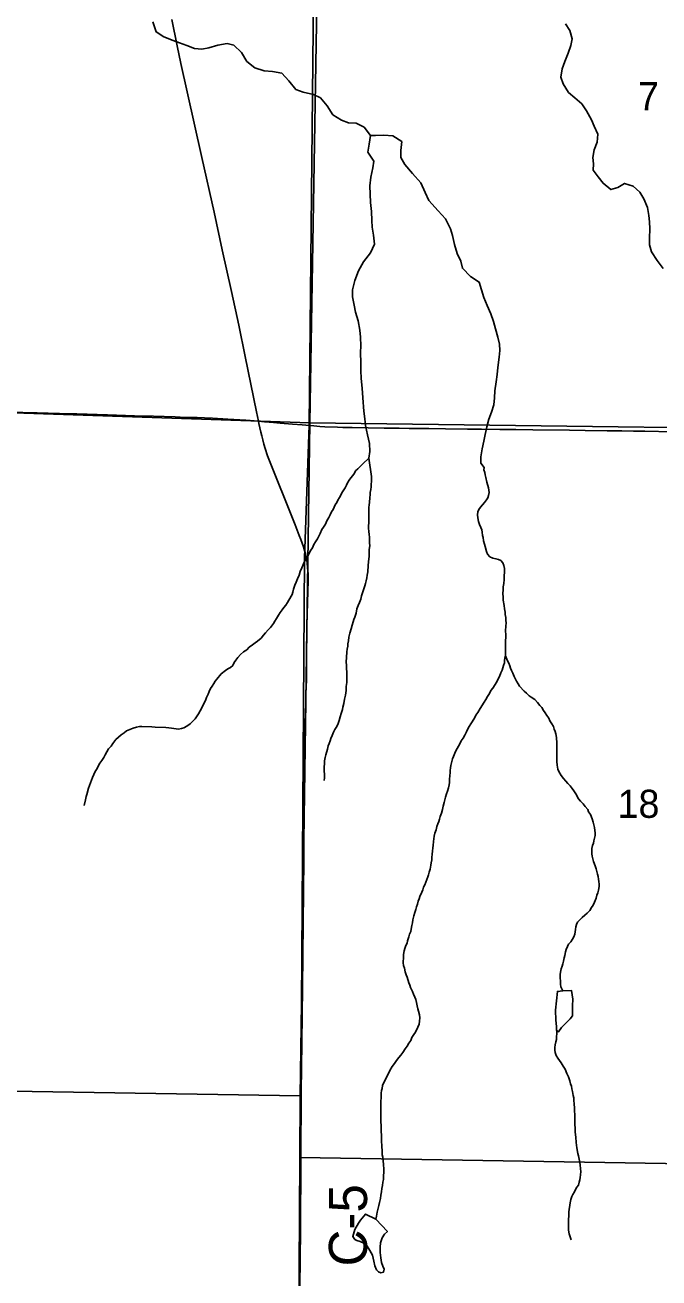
# Model space of a CAD drawing. Extents: x 0 to 34, y 0 to 22.
# Drawn here: x 3.044 to 3.988, y 15.009 to 16.874 of the extents above; entities that cross this region are included whole.
import ezdxf

# ---------------------------------------------------------------- set-up
doc = ezdxf.new("R2010")
doc.units = 0
for name, color, linetype in [('GM_X_Corporation', 7, 'Continuous'), ('GM_X_County_Road', 7, 'Continuous'), ('GM_X_County_Road_Text', 7, 'Continuous'), ('GM_X_Minor_River', 7, 'Continuous'), ('GM_X_Section_Text', 7, 'Continuous')]:
    doc.layers.add(name, color=color, linetype=linetype)

msp = doc.modelspace()

# ---------------------------------------------------------------- linework, layer by layer
at = {"layer": 'GM_X_Corporation'}
for points in [[(2.1, 18.3932), (2.1, 14.1), (3.4463, 14.1), (3.448, 14.3179), (3.4516, 14.7743), (3.4533, 15.0461), (3.4601, 16.0804), (3.4672, 16.2781), (3.4754, 17.1134)], [(3.4754, 17.1134), (3.4672, 16.2781), (3.4601, 16.0804), (3.4533, 15.0461), (3.4516, 14.7743), (3.448, 14.3179), (3.4463, 14.1), (8.9, 14.1)]]:
    msp.add_lwpolyline(points, dxfattribs=at)
for points in [[(3.4847, 17.2912), (3.4681, 16.2816), (2.4544, 16.3158), (2.4791, 17.2994)], [(4.475, 17.2762), (4.463, 16.2688), (3.4681, 16.2816), (3.4847, 17.2912)], [(2.4544, 16.3158), (3.4681, 16.2816), (3.4534, 15.28), (2.4405, 15.2964)], [(3.4681, 16.2816), (4.463, 16.2688), (4.4514, 15.172), (3.4532, 15.1884), (3.4534, 15.28)], [(2.4405, 15.2964), (3.4534, 15.28), (3.4532, 15.1884), (3.4477, 14.2699), (2.4377, 14.2835)], [(3.4532, 15.1884), (4.4514, 15.172), (4.4501, 14.1693), (3.4483, 14.1786), (3.4477, 14.2699)]]:
    msp.add_lwpolyline(points, close=True, dxfattribs=at)
at = {"layer": 'GM_X_County_Road'}
for points in [[(3.4613, 16.087), (3.4601, 16.0918), (3.4584, 16.0969), (3.4564, 16.1027), (3.4546, 16.1079), (3.4522, 16.1142), (3.446, 16.1298), (3.4052, 16.2326), (3.4015, 16.2433), (3.3996, 16.2499), (3.3979, 16.2564), (3.3965, 16.2623), (3.3952, 16.2677), (3.3935, 16.2744), (3.392, 16.2808), (3.3914, 16.2841), (3.3886, 16.2981), (3.3718, 16.3806), (3.3623, 16.427), (3.3513, 16.4769), (3.3376, 16.5393), (3.3254, 16.5952), (3.307, 16.6764), (3.2853, 16.7744), (3.2761, 16.8163), (3.2703, 16.8429), (3.2623, 16.8819)], [(3.0196, 16.2974), (3.0619, 16.2965), (3.0954, 16.2956), (3.1209, 16.2949), (3.1668, 16.2935), (3.2072, 16.2922), (3.2351, 16.2914), (3.2674, 16.2904), (3.2824, 16.2898), (3.3003, 16.2895), (3.3113, 16.2892), (3.3233, 16.2887), (3.3461, 16.2871), (3.3726, 16.2855), (3.3914, 16.2841), (3.4007, 16.2834), (3.4137, 16.2824), (3.4236, 16.2814), (3.4421, 16.2798), (3.4564, 16.2785), (3.4674, 16.2775)], [(3.4674, 16.2775), (3.4738, 16.277), (3.4831, 16.2763), (3.4905, 16.2759), (3.5091, 16.2751), (3.5172, 16.2748), (3.5308, 16.2746), (3.5787, 16.2739), (3.601, 16.2736), (3.6159, 16.2734), (3.6451, 16.2731), (3.67, 16.2728), (3.7029, 16.2724), (3.7234, 16.2721), (3.7507, 16.2719), (3.7749, 16.2718), (3.7998, 16.2715), (3.8544, 16.2707), (3.878, 16.2704), (3.9109, 16.2697), (3.9327, 16.2696), (3.9501, 16.2693), (3.9668, 16.2691), (4.0078, 16.2685)], [(3.4531, 14.9957), (3.4539, 15.0799), (3.4548, 15.1862), (3.4552, 15.2854), (3.4563, 15.3594), (3.4571, 15.4414), (3.4592, 15.6323), (3.4597, 15.7352), (3.4601, 15.8048), (3.4618, 15.8641), (3.4622, 15.8783), (3.4629, 15.899), (3.4629, 15.9319), (3.4636, 15.981), (3.4654, 16.0471), (3.4654, 16.0576), (3.4647, 16.0652), (3.4638, 16.0737), (3.4627, 16.0805), (3.4613, 16.087)]]:
    msp.add_lwpolyline(points, dxfattribs=at)
at = {"layer": 'GM_X_Minor_River'}
for points in [[(3.2344, 16.8784), (3.2394, 16.8635), (3.2505, 16.856), (3.2644, 16.8508), (3.2742, 16.8471), (3.2851, 16.8434), (3.2964, 16.839), (3.3074, 16.838), (3.3176, 16.8396), (3.331, 16.8438), (3.3451, 16.8461), (3.3549, 16.8436), (3.3664, 16.8327), (3.3744, 16.8196), (3.3863, 16.8102), (3.4002, 16.8053), (3.4124, 16.8047), (3.4263, 16.8021), (3.4367, 16.7908), (3.4474, 16.778), (3.4579, 16.774), (3.4737, 16.7702), (3.4838, 16.7654), (3.4938, 16.7534), (3.5022, 16.7403), (3.5152, 16.732), (3.5254, 16.7283), (3.5371, 16.7277), (3.5491, 16.7217), (3.5583, 16.7093), (3.5561, 16.6965), (3.5543, 16.6844), (3.5634, 16.6713), (3.562, 16.6614), (3.559, 16.6475), (3.5572, 16.6346), (3.5576, 16.6221), (3.5585, 16.6096), (3.5597, 16.5963), (3.5601, 16.583), (3.5606, 16.5727), (3.5629, 16.5609), (3.5645, 16.5476), (3.5581, 16.5345), (3.5479, 16.5215), (3.5404, 16.508), (3.5351, 16.4937), (3.5313, 16.4798), (3.5314, 16.4691), (3.5342, 16.4566), (3.5362, 16.4463), (3.54, 16.4337), (3.5424, 16.4196), (3.5436, 16.4093), (3.5437, 16.3964), (3.5434, 16.3865), (3.5438, 16.371), (3.5439, 16.3596), (3.5444, 16.3478), (3.5459, 16.3334), (3.5467, 16.319), (3.5485, 16.2992), (3.5497, 16.2874), (3.551, 16.2775), (3.554, 16.2638), (3.5567, 16.2508), (3.5572, 16.2391), (3.5558, 16.2292)], [(3.8488, 16.8755), (3.855, 16.8655), (3.8586, 16.8533), (3.8565, 16.8431), (3.8525, 16.8318), (3.8477, 16.8194), (3.8437, 16.8085), (3.8416, 16.796), (3.8452, 16.7864), (3.8529, 16.7734), (3.8627, 16.7653), (3.8727, 16.7564), (3.8798, 16.746), (3.8871, 16.7326), (3.8915, 16.723), (3.8966, 16.7115), (3.896, 16.6994), (3.8912, 16.6878), (3.8895, 16.6768), (3.8901, 16.6673), (3.8899, 16.6575), (3.8973, 16.6478), (3.9047, 16.6382), (3.9163, 16.6289), (3.9266, 16.6318), (3.9366, 16.638), (3.9494, 16.634), (3.9591, 16.6251), (3.9654, 16.6151), (3.9705, 16.6021), (3.9729, 16.5903), (3.9739, 16.5808), (3.9744, 16.5702), (3.9738, 16.5566), (3.9736, 16.5467), (3.9768, 16.5364), (3.9853, 16.5234), (3.9942, 16.5114)], [(3.5583, 16.7093), (3.5659, 16.7095), (3.5784, 16.7096), (3.5917, 16.7089), (3.6051, 16.7002), (3.6033, 16.687), (3.6034, 16.6764), (3.6092, 16.666), (3.621, 16.6528), (3.6332, 16.6388), (3.6396, 16.6243), (3.645, 16.6124), (3.6591, 16.5972), (3.6698, 16.5852), (3.6774, 16.5706), (3.6805, 16.5603), (3.6832, 16.547), (3.6874, 16.5336), (3.6928, 16.5225), (3.6952, 16.5118), (3.7074, 16.4993), (3.7201, 16.4911), (3.7271, 16.4681), (3.7318, 16.4563), (3.7375, 16.444), (3.7414, 16.4325), (3.7442, 16.4218), (3.7477, 16.4092), (3.7505, 16.3989), (3.751, 16.3891), (3.75, 16.3792), (3.7481, 16.3641), (3.7467, 16.3535), (3.7453, 16.3425), (3.7434, 16.3293), (3.7428, 16.3187), (3.7421, 16.3085), (3.7384, 16.2976), (3.7344, 16.2871), (3.7315, 16.2757), (3.7289, 16.2641), (3.7271, 16.2542), (3.7246, 16.2429), (3.7228, 16.2312), (3.7225, 16.2217)], [(3.472, 16.0955), (3.474, 16.1004), (3.4764, 16.1045), (3.4792, 16.109), (3.4832, 16.1172), (3.486, 16.1229), (3.4884, 16.1262), (3.4912, 16.1311), (3.4932, 16.1356), (3.4964, 16.1408), (3.4984, 16.1449), (3.5005, 16.1494), (3.5028, 16.1528), (3.5041, 16.1562), (3.5057, 16.1595), (3.508, 16.1629), (3.5097, 16.1666), (3.5121, 16.1708), (3.5141, 16.1741), (3.5157, 16.1775), (3.5204, 16.185), (3.5228, 16.1891), (3.5241, 16.1925), (3.5268, 16.1966), (3.5292, 16.1999), (3.532, 16.2033), (3.5343, 16.2066), (3.5359, 16.21), (3.5394, 16.2133), (3.5434, 16.2174), (3.5469, 16.2207), (3.5558, 16.2292)], [(3.4891, 15.7496), (3.4896, 15.7534), (3.4897, 15.758), (3.4891, 15.7641), (3.4893, 15.7698), (3.4898, 15.7743), (3.4899, 15.7785), (3.4908, 15.7834), (3.4917, 15.7876), (3.4942, 15.7958), (3.4955, 15.8008), (3.4967, 15.8045), (3.4984, 15.8083), (3.4992, 15.8117), (3.5012, 15.8162), (3.5033, 15.8211), (3.5053, 15.8252), (3.5081, 15.83), (3.5101, 15.8342), (3.5117, 15.8387), (3.5134, 15.8439), (3.5147, 15.8492), (3.5164, 15.8549), (3.5172, 15.8587), (3.5185, 15.8639), (3.5198, 15.8704), (3.5212, 15.8764), (3.5221, 15.8832), (3.5223, 15.8893), (3.5232, 15.895), (3.523, 15.8999), (3.5231, 15.9052), (3.5229, 15.9113), (3.5226, 15.9155), (3.5224, 15.9204), (3.5222, 15.9262), (3.5227, 15.9322), (3.523, 15.9409), (3.5235, 15.9447), (3.5244, 15.9493), (3.5245, 15.9527), (3.5254, 15.9572), (3.5263, 15.9625), (3.5276, 15.9689), (3.5293, 15.9753), (3.5309, 15.9806), (3.5326, 15.9855), (3.5335, 15.9889), (3.5351, 15.9923), (3.5368, 15.9983), (3.5381, 16.0047), (3.5401, 16.0096), (3.5418, 16.0145), (3.5438, 16.0194), (3.5451, 16.0243), (3.5484, 16.0348), (3.5501, 16.039), (3.5509, 16.0424), (3.5518, 16.0465), (3.5531, 16.0511), (3.5536, 16.0552), (3.5544, 16.0598), (3.5547, 16.0692), (3.5553, 16.0749), (3.5562, 16.0833), (3.5565, 16.0931), (3.5571, 16.0984), (3.5568, 16.103), (3.5569, 16.1072), (3.5567, 16.1114), (3.5564, 16.1156), (3.5558, 16.1198), (3.5555, 16.1247), (3.5559, 16.1365), (3.5556, 16.1418), (3.556, 16.1555), (3.5565, 16.1596), (3.557, 16.163), (3.5572, 16.1706), (3.5577, 16.1744), (3.5578, 16.1782), (3.5587, 16.1824), (3.5592, 16.1865), (3.5593, 16.1907), (3.5598, 16.1941), (3.5599, 16.1975), (3.5596, 16.2017), (3.5558, 16.2292)], [(3.7522, 16.077), (3.7489, 16.0782), (3.7451, 16.0795), (3.7402, 16.0804), (3.7361, 16.0824), (3.7324, 16.0863), (3.731, 16.0901), (3.7289, 16.0978), (3.7279, 16.1012), (3.7265, 16.1062), (3.7259, 16.1108), (3.7252, 16.1142), (3.7246, 16.1188), (3.7239, 16.1222), (3.7225, 16.1261), (3.7207, 16.1303), (3.7193, 16.1349), (3.718, 16.1403), (3.7174, 16.1448), (3.7179, 16.1494), (3.7195, 16.1528), (3.7222, 16.1561), (3.725, 16.1598), (3.7281, 16.1632), (3.7309, 16.1669), (3.7329, 16.1702), (3.7341, 16.1736), (3.735, 16.1778), (3.7347, 16.1816), (3.7341, 16.185), (3.7313, 16.1935), (3.7299, 16.2003), (3.7289, 16.2042), (3.7283, 16.208), (3.7272, 16.2118), (3.7273, 16.2152), (3.7225, 16.2217)], [(3.1321, 15.7122), (3.1339, 15.7205), (3.1352, 15.7254), (3.136, 15.7288), (3.1386, 15.7378), (3.1402, 15.742), (3.1414, 15.7457), (3.1427, 15.7499), (3.1443, 15.754), (3.1463, 15.7581), (3.1484, 15.7627), (3.1512, 15.7671), (3.1531, 15.7705), (3.1556, 15.775), (3.1583, 15.7791), (3.1611, 15.7836), (3.1635, 15.7877), (3.1659, 15.7922), (3.1683, 15.7963), (3.1722, 15.8004), (3.1746, 15.8045), (3.1793, 15.8104), (3.1832, 15.8141), (3.1871, 15.8174), (3.1914, 15.8203), (3.1952, 15.8233), (3.1999, 15.8254), (3.2052, 15.8272), (3.2098, 15.8286), (3.2144, 15.8296), (3.2178, 15.8299), (3.2326, 15.8294), (3.2379, 15.8289), (3.2534, 15.8285), (3.258, 15.828), (3.2621, 15.8275), (3.2723, 15.826), (3.2769, 15.8267), (3.2804, 15.8277), (3.285, 15.8302), (3.2896, 15.8335), (3.2928, 15.8369), (3.2974, 15.8413), (3.3022, 15.8488), (3.3046, 15.8532), (3.3066, 15.8566), (3.3106, 15.8649), (3.3126, 15.8686), (3.3143, 15.8731), (3.3167, 15.878), (3.3183, 15.8817), (3.3203, 15.8862), (3.3227, 15.8896), (3.3251, 15.8937), (3.3271, 15.8971), (3.3295, 15.9004), (3.3361, 15.9082), (3.3423, 15.913), (3.3458, 15.9155), (3.3497, 15.9177), (3.3532, 15.9207), (3.3552, 15.9248), (3.3576, 15.9285), (3.3607, 15.9326), (3.365, 15.9367), (3.3693, 15.9407), (3.374, 15.944), (3.3779, 15.9477), (3.3825, 15.9514), (3.3864, 15.9543), (3.3903, 15.9568), (3.3953, 15.9613), (3.3992, 15.9657), (3.402, 15.9694), (3.4059, 15.9735), (3.4094, 15.9772), (3.4138, 15.9832), (3.4158, 15.9865), (3.4185, 15.9906), (3.4213, 15.9955), (3.4237, 15.9992), (3.4269, 16.0033), (3.4293, 16.007), (3.4324, 16.0104), (3.4348, 16.0141), (3.4368, 16.0179), (3.4416, 16.0261), (3.4428, 16.0298), (3.4437, 16.034), (3.4457, 16.04), (3.4478, 16.0445), (3.4498, 16.0494), (3.4519, 16.055), (3.4535, 16.0603), (3.4563, 16.0659), (3.4584, 16.072), (3.4608, 16.0764), (3.4636, 16.0806), (3.4652, 16.0839), (3.4696, 16.0922), (3.472, 16.0955)], [(3.6362, 15.5867), (3.6371, 15.5904), (3.6391, 15.5942), (3.6408, 15.5983), (3.6436, 15.6058), (3.6449, 15.6092), (3.6457, 15.613), (3.647, 15.6175), (3.6483, 15.6236), (3.6488, 15.627), (3.6497, 15.6315), (3.6498, 15.6349), (3.6503, 15.6398), (3.6504, 15.6444), (3.6509, 15.6493), (3.6514, 15.6527), (3.652, 15.6588), (3.6528, 15.6626), (3.6533, 15.6667), (3.6542, 15.6709), (3.6559, 15.6758), (3.6571, 15.6807), (3.6588, 15.6848), (3.66, 15.6882), (3.6612, 15.692), (3.6621, 15.6957), (3.6638, 15.7006), (3.6654, 15.7063), (3.6667, 15.7112), (3.668, 15.7165), (3.6689, 15.7206), (3.6701, 15.7248), (3.6714, 15.7297), (3.673, 15.7334), (3.6743, 15.7387), (3.6752, 15.7429), (3.6757, 15.7463), (3.6758, 15.7516), (3.6763, 15.7561), (3.6769, 15.7611), (3.677, 15.7645), (3.6774, 15.7683), (3.6779, 15.7717), (3.6788, 15.7758), (3.6805, 15.7815), (3.6817, 15.7849), (3.685, 15.7924), (3.6874, 15.7972), (3.6914, 15.804), (3.6934, 15.8085), (3.6962, 15.8126), (3.6989, 15.8171), (3.7014, 15.8219), (3.7034, 15.8261), (3.7054, 15.8298), (3.7078, 15.8339), (3.7133, 15.8421), (3.7153, 15.8466), (3.7181, 15.8507), (3.7217, 15.8563), (3.7273, 15.866), (3.73, 15.8698), (3.7324, 15.8746), (3.7356, 15.8791), (3.7376, 15.8832), (3.7404, 15.8869), (3.7463, 15.8963), (3.748, 15.8997), (3.7504, 15.9041), (3.7524, 15.9094), (3.7544, 15.9135), (3.7561, 15.9203), (3.7578, 15.9245), (3.7579, 15.9279), (3.7583, 15.9313), (3.7592, 15.9347), (3.7593, 15.9381), (3.7594, 15.9419), (3.7595, 15.9464), (3.7593, 15.9533), (3.7597, 15.9666), (3.7595, 15.9715), (3.7597, 15.9795), (3.7602, 15.9833), (3.76, 15.9882), (3.7597, 15.992), (3.759, 15.9962), (3.7588, 16), (3.7578, 16.005), (3.7571, 16.0096), (3.7559, 16.018), (3.7556, 16.0222), (3.7554, 16.0275), (3.7559, 16.0332), (3.756, 16.0374), (3.7566, 16.0427), (3.7571, 16.0483), (3.7576, 16.0651), (3.7566, 16.0696), (3.7555, 16.0731), (3.7522, 16.077)], [(3.8698, 15.5421), (3.8734, 15.5454), (3.8776, 15.5491), (3.8811, 15.552), (3.8847, 15.5561), (3.8874, 15.5606), (3.8898, 15.5639), (3.8918, 15.5684), (3.8943, 15.5741), (3.8955, 15.5786), (3.8968, 15.5824), (3.8977, 15.5861), (3.8986, 15.5914), (3.8987, 15.5952), (3.8984, 15.599), (3.8977, 15.6025), (3.8975, 15.6067), (3.8964, 15.6101), (3.8954, 15.6139), (3.8944, 15.6181), (3.893, 15.6224), (3.8905, 15.6289), (3.8891, 15.6327), (3.8881, 15.6366), (3.8878, 15.6404), (3.8876, 15.6446), (3.888, 15.648), (3.8889, 15.6525), (3.8902, 15.6563), (3.891, 15.6597), (3.8919, 15.6634), (3.8928, 15.6676), (3.8929, 15.671), (3.8916, 15.6794), (3.8909, 15.6832), (3.8899, 15.6874), (3.8882, 15.6924), (3.8857, 15.6986), (3.8831, 15.7028), (3.8817, 15.7063), (3.8777, 15.7106), (3.8747, 15.7145), (3.8711, 15.7184), (3.8681, 15.7219), (3.8638, 15.7296), (3.8609, 15.7338), (3.8587, 15.7373), (3.8554, 15.7416), (3.8521, 15.7447), (3.8492, 15.7486), (3.8455, 15.7525), (3.8422, 15.7568), (3.8389, 15.7626), (3.8371, 15.7664), (3.8362, 15.7722), (3.8356, 15.7775), (3.8357, 15.7824), (3.8358, 15.7866), (3.8355, 15.7904), (3.8357, 15.7961), (3.8355, 15.8007), (3.8356, 15.8049), (3.8351, 15.8132), (3.8341, 15.8186), (3.833, 15.8224), (3.832, 15.8259), (3.8306, 15.8297), (3.8284, 15.8336), (3.8255, 15.8382), (3.8237, 15.842), (3.8208, 15.8459), (3.8183, 15.8502), (3.8157, 15.8537), (3.8136, 15.8579), (3.8102, 15.861), (3.8069, 15.8653), (3.8029, 15.87), (3.7977, 15.8732), (3.7943, 15.8755), (3.7906, 15.8795), (3.7873, 15.8822), (3.7803, 15.8896), (3.7781, 15.8931), (3.7756, 15.897), (3.7742, 15.9004), (3.772, 15.9043), (3.7702, 15.9093), (3.7684, 15.9131), (3.7667, 15.9166), (3.7656, 15.9201), (3.7642, 15.9239), (3.7624, 15.9277), (3.7592, 15.9347)], [(3.5663, 15.0966), (3.5671, 15.1011), (3.5684, 15.1068), (3.5692, 15.1109), (3.5709, 15.1169), (3.5718, 15.1215), (3.5731, 15.1271), (3.5736, 15.1321), (3.5746, 15.1374), (3.5754, 15.1423), (3.576, 15.1468), (3.5768, 15.1514), (3.5777, 15.1555), (3.5782, 15.1722), (3.5776, 15.1768), (3.5774, 15.1844), (3.5768, 15.1886), (3.5757, 15.1924), (3.5755, 15.1962), (3.575, 15.2069), (3.5748, 15.2118), (3.5749, 15.2171), (3.5747, 15.2221), (3.5744, 15.2267), (3.574, 15.2366), (3.5737, 15.2411), (3.5738, 15.2453), (3.5736, 15.2502), (3.5739, 15.2609), (3.5736, 15.2651), (3.5742, 15.284), (3.5746, 15.2878), (3.5755, 15.2912), (3.5764, 15.2954), (3.578, 15.2999), (3.58, 15.3036), (3.5816, 15.307), (3.584, 15.3115), (3.5873, 15.3179), (3.5905, 15.3239), (3.594, 15.3283), (3.5968, 15.3328), (3.6003, 15.3373), (3.6035, 15.3406), (3.6066, 15.3447), (3.6098, 15.3499), (3.6129, 15.354), (3.6154, 15.3585), (3.6185, 15.3626), (3.6201, 15.3667), (3.6229, 15.3712), (3.6253, 15.3749), (3.6286, 15.3824), (3.6306, 15.3869), (3.6315, 15.3911), (3.632, 15.396), (3.6313, 15.4006), (3.63, 15.4063), (3.629, 15.4098), (3.6279, 15.414), (3.6269, 15.419), (3.6256, 15.4236), (3.6241, 15.427), (3.6224, 15.4313), (3.621, 15.4355), (3.6181, 15.4413), (3.6167, 15.4447), (3.6156, 15.4482), (3.6128, 15.4566), (3.6114, 15.4604), (3.61, 15.4647), (3.6087, 15.47), (3.6076, 15.4739), (3.607, 15.478), (3.6072, 15.4872), (3.6073, 15.4906), (3.6086, 15.4959), (3.6095, 15.4996), (3.6111, 15.5038), (3.6128, 15.5075), (3.6136, 15.5109), (3.6153, 15.5166), (3.6165, 15.5207), (3.6182, 15.5249), (3.619, 15.5282), (3.6199, 15.5335), (3.6208, 15.5377), (3.6213, 15.5419), (3.623, 15.5479), (3.6243, 15.5528), (3.6256, 15.5573), (3.6268, 15.5615), (3.6281, 15.5652), (3.6293, 15.5698), (3.6306, 15.5731), (3.6318, 15.5769), (3.6346, 15.5833), (3.6362, 15.5867)], [(3.8416, 15.4424), (3.8416, 15.4426), (3.8413, 15.446), (3.8411, 15.4502), (3.8405, 15.4563), (3.8406, 15.4608), (3.8411, 15.4642), (3.8424, 15.4691), (3.8436, 15.4729), (3.8445, 15.4767), (3.8457, 15.4804), (3.8466, 15.4854), (3.8475, 15.4891), (3.8488, 15.4944), (3.8496, 15.4978), (3.8516, 15.5023), (3.8533, 15.5057), (3.8564, 15.5094), (3.8592, 15.5131), (3.8612, 15.5165), (3.8624, 15.5206), (3.8634, 15.5274), (3.8642, 15.5316), (3.8651, 15.535), (3.8667, 15.5384), (3.8698, 15.5421)], [(3.8416, 15.4424), (3.8445, 15.4363)], [(3.8445, 15.4363), (3.8365, 15.4354), (3.8338, 15.4074), (3.8341, 15.3925), (3.835, 15.3834), (3.8352, 15.3781), (3.8359, 15.3769), (3.8381, 15.3753), (3.8429, 15.3816), (3.8492, 15.3883), (3.8554, 15.3946), (3.859, 15.399)], [(3.859, 15.399), (3.859, 15.4138), (3.8593, 15.4241), (3.8574, 15.437), (3.8445, 15.4363)], [(3.8571, 15.0659), (3.8557, 15.0705), (3.8539, 15.0748), (3.8533, 15.0801), (3.8531, 15.085), (3.8533, 15.0911), (3.853, 15.0953), (3.8536, 15.1025), (3.8537, 15.1074), (3.8556, 15.1211), (3.8565, 15.126), (3.8582, 15.1301), (3.8594, 15.1335), (3.8618, 15.1372), (3.8634, 15.1406), (3.8654, 15.144), (3.8678, 15.1473), (3.869, 15.1515), (3.8699, 15.1549), (3.8707, 15.1586), (3.8708, 15.1624), (3.8714, 15.1677), (3.8711, 15.1716), (3.8705, 15.1773), (3.8698, 15.1811), (3.8692, 15.1857), (3.8678, 15.1906), (3.8668, 15.1945), (3.8655, 15.2029), (3.8646, 15.2105), (3.8641, 15.2185), (3.8632, 15.2261), (3.863, 15.2326), (3.8627, 15.2368), (3.8625, 15.2425), (3.8626, 15.2467), (3.8624, 15.2512), (3.8622, 15.2584), (3.8619, 15.2619), (3.8617, 15.268), (3.8611, 15.2733), (3.8608, 15.2771), (3.8602, 15.2805), (3.8592, 15.2866), (3.8582, 15.2905), (3.8575, 15.2943), (3.8561, 15.2981), (3.8551, 15.3023), (3.853, 15.3085), (3.8508, 15.3135), (3.848, 15.3196), (3.8451, 15.3243), (3.8422, 15.3293), (3.8371, 15.3363), (3.8345, 15.3402), (3.8331, 15.3444), (3.8325, 15.3482), (3.8326, 15.352), (3.8331, 15.3558), (3.834, 15.3603), (3.8352, 15.3641), (3.8359, 15.3769)], [(3.5483, 15.0608), (3.5431, 15.0633), (3.5378, 15.0649), (3.5348, 15.0665), (3.5319, 15.0708), (3.5352, 15.081), (3.5405, 15.0907), (3.5436, 15.0951), (3.5507, 15.104), (3.5663, 15.0966)], [(3.5663, 15.0966), (3.5834, 15.0784), (3.5794, 15.0743), (3.5755, 15.0687), (3.573, 15.0612), (3.5728, 15.0551), (3.5729, 15.0468), (3.5735, 15.0388), (3.5748, 15.0323), (3.5769, 15.0265), (3.5786, 15.0219), (3.5778, 15.0178), (3.5736, 15.0168), (3.5702, 15.018), (3.5672, 15.0211), (3.5647, 15.0269), (3.5631, 15.0342), (3.5614, 15.043), (3.5571, 15.0499), (3.5535, 15.0565), (3.5483, 15.0608)]]:
    msp.add_lwpolyline(points, dxfattribs=at)

# ---------------------------------------------------------------- texts
at = {"layer": 'GM_X_County_Road_Text'}
msp.add_text('C-5', height=0.05682, rotation=90, dxfattribs=at).set_placement((3.5532, 15.0262))
at = {"layer": 'GM_X_Section_Text'}
for s, height, p in [('7', 0.0419, (3.9566, 16.7468)), ('18', 0.04186, (3.9262, 15.6938))]:
    msp.add_text(s, height=height, rotation=0, dxfattribs=at).set_placement(p)

doc.saveas('drawing.dxf')
